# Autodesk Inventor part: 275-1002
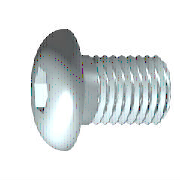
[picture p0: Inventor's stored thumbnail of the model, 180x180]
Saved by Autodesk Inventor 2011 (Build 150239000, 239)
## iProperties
IsCustomPart: 0
Company: Autodesk Inc.
Created: 2010-02
Part Number: 275-1002
Material: Steel, Mild
Description: Hexagon Socket Button Head Cap Screw
Document SubType Name: Modeling
Standard: ANSI B18.3
Designer: Phil
Standard Revision: 2003
Standards Organization: ANSI
Language: en-US
Size Designation: 8 - 32 x 1/4
Categories: <MemberInstance><Categories><Category DisplayName="Fasteners" InternalName="e4da775c-781d-43d5-af7c-5136215cf5a6" Mnemonic="FSTN"><Category DisplayName="Bolts"
Density: 1 g/cm^3
Catalog Web Link: http://www.vexrobotics.com/screws-8-32.html
Vendor: Innovation First, Inc.
Author: Autodesk Inc.
Title: VEX Robotics Kit of Parts
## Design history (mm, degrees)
workplane "Work Plane1"
fillet "Fillet2" dims "d30" = 0.1 (= R)
revolve "Body" stored, may be unused: angle "d10" = 90 deg
sketch "Sketch2"
  geometry: L1 (0, -5.547)-(0, 5.547) reference; L2 (-5.547, 0)-(5.547, 0) reference; L3 (1.378, 0)-(0.689, -1.194); L4 (0.689, -1.194)-(-0.689, -1.194); L5 (-0.689, -1.194)-(-1.378, 0); L6 (-1.378, 0)-(-0.689, 1.194); L7 (-0.689, 1.194)-(0.689, 1.194); L8 (0.689, 1.194)-(1.378, 0); 2 further points
  constraints: 12 end point, 1 coincident, 1 horizontal alignment, 1 point on line, 12 other
extrude "Slot" join sketch "Sketch2" stored distance "d11" = 10; taper "d12" = 0 deg
body "Solid1"
fillet "Fillet1" dims "d17" = 1.9558 (= RR)
feature "Thread" dims "d13" = 4.75976 (= GEL), "d14" = 0
chamfer "Chamfer1" distance "d15" = 0.48692 (= -0.5 x SPD + 0.5 x GD); stored, may be unused: second distance "d16" = 0.48692 (= GUL), angle "d27" = 45 deg
sketch "Sketch1"
  geometry: L1 (-0.093, 0)-(6.35, 0); L2 (6.35, 0)-(6.35, 2.083); L3 (6.35, 2.083)-(1.59, 2.083); L4 (1.59, 2.083)-(0, 2.083); L5 (0, 2.083)-(0, 2.083); L6 (0, 2.083)-(0, 3.962); L7 (0, 3.962)-(-2.21, 3.962); L8 (-2.21, 3.962)-(-2.21, 1.378); L9 (-2.21, 1.378)-(-0.889, 1.378); L10 (-0.889, 1.378)-(-0.093, 0); L11 (-3.922, 0)-(8.062, 0) reference; L12 (0, -0.792)-(0, 4.755) reference; L13 (1.59, 2.083)-(0, 2.083)
  constraints: 22 end point, 6 parallel, 2 collinear, 2 perpendicular, 1 horizontal, 1 point on line
  dimensions: "d1" = 4.75976 distance from line of L3.end L2 (= GEL); "d2" = 1.59014 distance of L4.end L3.end (computed from GAL); "d3" = 2.2098 distance between parallel lines of L8 L6 (= KOH); "d4" = 1.3208 distance of L8.end L9.end (= INTI); "d5" = 60 deg angle of L10 L1; "d6" = 4.1656 diameter of L3 L1 (= GD); "d7" = 4.1656 diameter of L5 L1 (= BDM); "d8" = 2.75696 diameter of L9 L1 (= 1.1547 x SW); "d9" = 7.9248 diameter of L7 L1 (= KOD); "d26" = 6.35 distance between parallel lines of L12 L2 (= NLG)
other parameters: "GD" = 4.1656 (= NND) [user parameter; used in 2 equation terms], "NLG" = 6.35 [user parameter; used in 1 equation term], "GEL" = 4.75976 [user parameter; used in 2 equation terms], "KOD" = 7.9248 [user parameter; used in 1 equation term], "KOH" = 2.2098 [user parameter; used in 1 equation term], "INTI" = 1.3208 [user parameter; used in 1 equation term], "GAL" = 1.59004 [user parameter; used in 1 equation term], "GUL" = 0.48692 [user parameter; used in 1 equation term], "BDM" = 4.1656 (= NND) [user parameter; used in 1 equation term], "SW" = 2.3876 [user parameter; used in 1 equation term], "RR" = 1.9558 [user parameter; used in 1 equation term], "SPD" = 3.19176 [user parameter; used in 2 equation terms], "d19" = 0, "d28" = 0, "d29" = 0, "R" = 0.1 [user parameter; used in 1 equation term], "TOA" = 30 deg [user parameter], "GD1" = 3.19176 (= SPD) [user parameter], "THREADDIA" = 4.1656 [user parameter], "PTC" = 0.79375 (computed from TPU) [user parameter], "KOH1" = 0.381 [user parameter], "NND" = 4.1656 [user parameter; used in 2 equation terms], "E0" = 2.75768 [user parameter]
